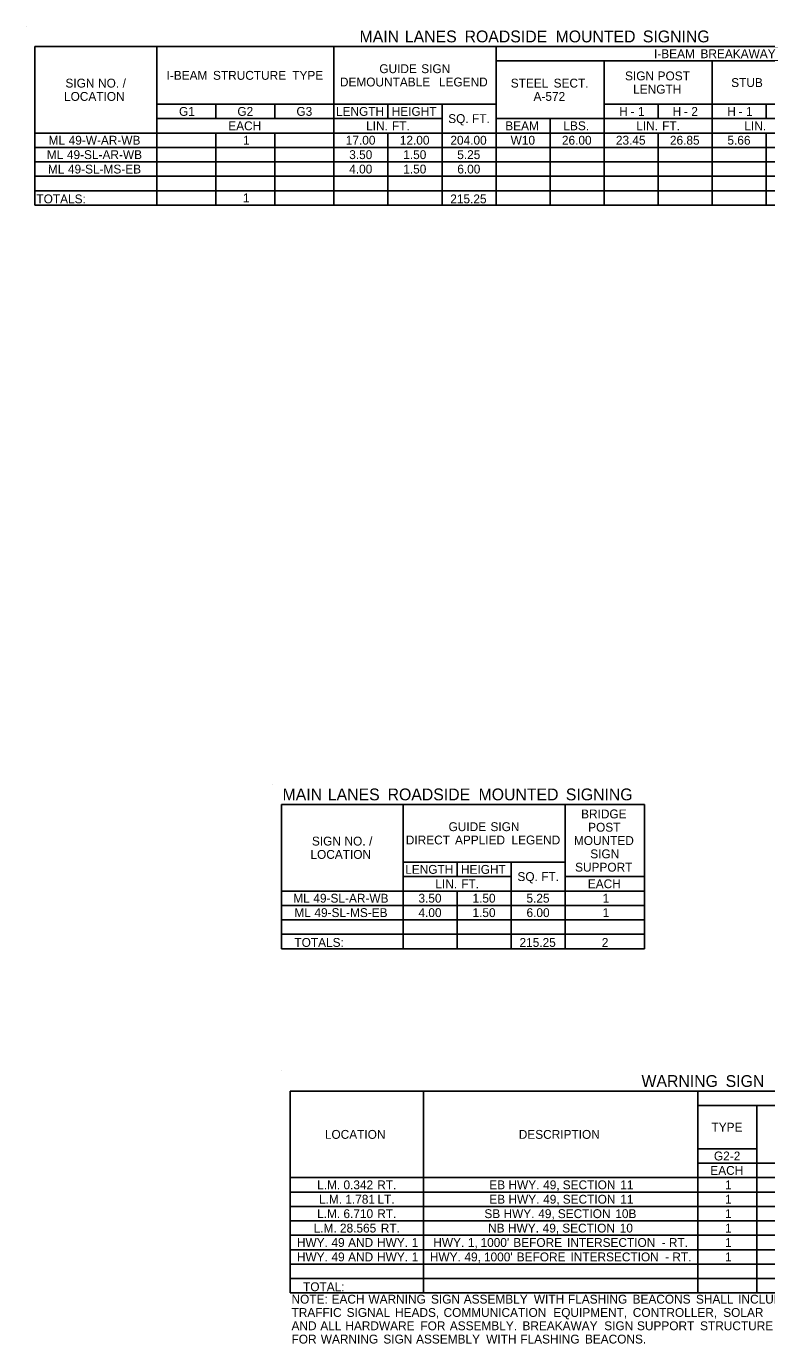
# Model space of a CAD drawing. Extents: x 229 to 4210, y 35 to 1715.
# Drawn here: x 2341 to 2842, y 368 to 1259 of the extents above; entities that cross this region are included whole.
import ezdxf

# ---------------------------------------------------------------- set-up
doc = ezdxf.new("R2010")
doc.units = 0
doc.layers.add('B_Steel Hidden', color=7, linetype='Continuous')
doc.layers.add('Default', color=7, linetype='Continuous')

msp = doc.modelspace()

# ---------------------------------------------------------------- linework, layer by layer
at = {"layer": 'B_Steel Hidden'}
for p, q in [((2341.48, 1259.36), (2341.48, 1259.36)), ((2508.25, 746.71), (2508.25, 746.71)), ((2514.1, 552.85), (2514.1, 552.85))]:
    msp.add_line(p, q, dxfattribs=at)
at = {"layer": 'Default'}
for p, q in [((2347.33, 1245.71), (3024.95, 1245.71)), ((2347.33, 1138.46), (2347.33, 1245.71)), ((2347.33, 1138.46), (2347.33, 1245.71)), ((2429.71, 1138.46), (2429.71, 1245.71)), ((2549.64, 1138.46), (2549.64, 1245.71)), ((2659.33, 1138.46), (2659.33, 1245.71)), ((2659.33, 1235.96), (3024.95, 1235.96)), ((2732.45, 1138.46), (2732.45, 1235.96)), ((2805.58, 1206.71), (2805.58, 1235.96)), ((2805.58, 1138.46), (2805.58, 1235.96)), ((2429.71, 1206.71), (2659.33, 1206.71)), ((2469.69, 1196.96), (2469.69, 1206.71)), ((2509.66, 1196.96), (2509.66, 1206.71)), ((2586.2, 1196.96), (2586.2, 1206.71)), ((2622.76, 1138.46), (2622.76, 1206.71)), ((2732.45, 1206.71), (2988.39, 1206.71)), ((2769.01, 1196.96), (2769.01, 1206.71)), ((2842.14, 1196.96), (2842.14, 1206.71)), ((2429.71, 1196.96), (2622.76, 1196.96)), ((2659.33, 1196.96), (3024.95, 1196.96)), ((2695.89, 1138.46), (2695.89, 1196.96)), ((2732.45, 1196.96), (2769.01, 1196.96)), ((2769.01, 1196.96), (2805.58, 1196.96)), ((2805.58, 1196.96), (2842.14, 1196.96)), ((2805.58, 1148.21), (2805.58, 1196.96)), ((2842.14, 1196.96), (2988.39, 1196.96)), ((2347.33, 1187.21), (3024.95, 1187.21)), ((2429.71, 1138.46), (2429.71, 1187.21)), ((2469.69, 1148.21), (2469.69, 1187.21)), ((2469.69, 1138.46), (2469.69, 1187.21)), ((2509.66, 1148.21), (2509.66, 1187.21)), ((2509.66, 1138.46), (2509.66, 1187.21)), ((2549.64, 1148.21), (2549.64, 1187.21)), ((2586.2, 1148.21), (2586.2, 1187.21)), ((2586.2, 1138.46), (2586.2, 1187.21)), ((2622.76, 1187.21), (3024.95, 1187.21)), ((2622.76, 1148.21), (2622.76, 1187.21)), ((2659.33, 1148.21), (2659.33, 1187.21)), ((2695.89, 1148.21), (2695.89, 1187.21)), ((2732.45, 1148.21), (2732.45, 1187.21)), ((2769.01, 1148.21), (2769.01, 1187.21)), ((2769.01, 1138.46), (2769.01, 1187.21)), ((2842.14, 1148.21), (2842.14, 1187.21)), ((2842.14, 1138.46), (2842.14, 1187.21)), ((2347.33, 1177.46), (3024.95, 1177.46)), ((2347.33, 1167.71), (3024.95, 1167.71)), ((2347.33, 1157.96), (3024.95, 1157.96)), ((2347.33, 1148.21), (3024.95, 1148.21)), ((2347.33, 1148.21), (3024.95, 1148.21)), ((2347.33, 1138.46), (3024.95, 1138.46)), ((2514.1, 733.06), (2759.8, 733.06)), ((2514.1, 635.56), (2514.1, 733.06)), ((2514.1, 635.56), (2514.1, 733.06)), ((2596.49, 635.56), (2596.49, 733.06)), ((2706.18, 635.56), (2706.18, 733.06)), ((2759.8, 635.56), (2759.8, 733.06)), ((2596.49, 694.06), (2706.18, 694.06)), ((2633.05, 684.31), (2633.05, 694.06)), ((2669.61, 635.56), (2669.61, 694.06)), ((2596.49, 684.31), (2669.61, 684.31)), ((2706.18, 684.31), (2759.8, 684.31)), ((2514.1, 674.56), (2706.18, 674.56)), ((2596.49, 635.56), (2596.49, 674.56)), ((2633.05, 645.31), (2633.05, 674.56)), ((2633.05, 635.56), (2633.05, 674.56)), ((2669.61, 674.56), (2759.8, 674.56)), ((2669.61, 645.31), (2669.61, 674.56)), ((2706.18, 674.56), (2759.8, 674.56)), ((2706.18, 645.31), (2706.18, 674.56)), ((2514.1, 664.81), (2759.8, 664.81)), ((2514.1, 655.06), (2759.8, 655.06)), ((2514.1, 645.31), (2759.8, 645.31)), ((2514.1, 645.31), (2759.8, 645.31)), ((2514.1, 635.56), (2759.8, 635.56)), ((2519.95, 539.2), (3293.13, 539.2)), ((2519.95, 402.7), (2519.95, 539.2)), ((2519.95, 402.7), (2519.95, 539.2)), ((2610.14, 402.7), (2610.14, 539.2)), ((2795.88, 402.7), (2795.88, 539.2)), ((2795.88, 529.45), (3201.48, 529.45)), ((2835.85, 402.7), (2835.85, 529.45)), ((2795.88, 500.2), (2835.85, 500.2)), ((2795.88, 490.45), (3164.91, 490.45)), ((2795.88, 402.7), (2795.88, 490.45)), ((2835.85, 412.45), (2835.85, 490.45)), ((2519.95, 480.7), (3293.13, 480.7)), ((2610.14, 402.7), (2610.14, 480.7)), ((2519.95, 470.95), (3293.13, 470.95)), ((2519.95, 461.2), (3293.13, 461.2)), ((2519.95, 451.45), (3293.13, 451.45)), ((2519.95, 441.7), (3293.13, 441.7)), ((2519.95, 431.95), (3293.13, 431.95)), ((2519.95, 422.2), (3293.13, 422.2)), ((2519.95, 412.45), (3293.13, 412.45)), ((2519.95, 412.45), (3293.13, 412.45)), ((2519.95, 402.7), (3293.13, 402.7))]:
    msp.add_line(p, q, dxfattribs=at)

# ---------------------------------------------------------------- texts
for s, height, p in [('MAIN', 8, (2566.96, 1248.53)), (' LANES', 8, (2594.63, 1248.53)), (' ROADSIDE', 8, (2635.07, 1248.53)), (' MOUNTED', 8, (2696.63, 1248.53)), (' SIGNING', 8, (2755.69, 1248.53)), ('I-BEAM', 6, (2766.23, 1237.83)), (' BREAKAWAY', 6, (2795.44, 1237.83)), ('GUIDE', 6, (2580.34, 1227.71)), (' SIGN', 6, (2606.47, 1227.71)), ('SIGN', 6, (2367.95, 1217.96)), (' NO.', 6, (2387.77, 1217.96)), (' /', 6, (2404.43, 1217.96)), ('I-BEAM', 6, (2436.36, 1223.21)), (' STRUCTURE', 6, (2465.56, 1223.21)), (' TYPE', 6, (2519.18, 1223.21)), ('DEMOUNTABLE', 6, (2553.66, 1218.71)), (' LEGEND', 6, (2618.45, 1218.71)), ('STEEL', 6, (2669.28, 1217.96)), (' SECT.', 6, (2696.05, 1217.96)), ('SIGN', 6, (2746.61, 1222.83)), (' POST', 6, (2766.43, 1222.83)), ('STUB', 6, (2818.44, 1218.33)), ('LOCATION', 6, (2366.97, 1208.96)), ('A-572', 6, (2684.69, 1208.96)), ('LENGTH', 6, (2752.1, 1213.83)), ('G1', 6, (2444.79, 1198.83)), ('G2', 6, (2484.3, 1198.83)), ('G3', 6, (2524.24, 1198.83)), ('LENGTH', 6, (2551.01, 1198.83)), ('HEIGHT', 6, (2588.73, 1198.83)), ('H', 6, (2742.68, 1198.83)), (' 1', 6, (2753.15, 1198.83)), ('H', 6, (2778.78, 1198.83)), (' 2', 6, (2789.25, 1198.83)), ('H', 6, (2815.81, 1198.83)), (' 1', 6, (2826.28, 1198.83)), ('EACH', 6, (2478.12, 1189.08)), ('LIN.', 6, (2571.41, 1189.08)), (' FT.', 6, (2586.67, 1189.08)), ('SQ.', 6, (2626.95, 1193.96)), (' FT.', 6, (2640.82, 1193.96)), ('BEAM', 6, (2665.56, 1189.08)), ('LBS.', 6, (2704.91, 1189.08)), (' -', 6, (2748.09, 1198.83)), ('LIN.', 6, (2754.22, 1189.08)), (' FT.', 6, (2769.48, 1189.08)), (' -', 6, (2784.19, 1198.83)), (' -', 6, (2821.22, 1198.83)), ('LIN.', 6, (2827.35, 1189.08)), ('ML', 6, (2356.53, 1179.33)), (' 49-W-AR-WB', 6, (2367.88, 1179.33)), ('1', 6, (2488.12, 1179.33)), ('17.00', 6, (2557.64, 1179.33)), ('12.00', 6, (2594.2, 1179.33)), ('204.00', 6, (2628.43, 1179.33)), ('W10', 6, (2669.19, 1179.33)), ('26.00', 6, (2703.89, 1179.33)), ('23.45', 6, (2740.42, 1179.33)), ('26.85', 6, (2776.98, 1179.33)), ('5.66', 6, (2815.89, 1179.33)), ('ML', 6, (2355.36, 1169.58)), (' 49-SL-AR-WB', 6, (2366.71, 1169.58)), ('3.50', 6, (2559.97, 1169.58)), ('1.50', 6, (2596.53, 1169.58)), ('5.25', 6, (2633.06, 1169.58)), ('ML', 6, (2356.06, 1159.83)), (' 49-SL-MS-EB', 6, (2367.4, 1159.83)), ('4.00', 6, (2559.97, 1159.83)), ('1.50', 6, (2596.53, 1159.83)), ('6.00', 6, (2633.09, 1159.83)), ('TOTALS:', 6, (2348.3, 1139.66)), ('1', 6, (2488.03, 1140.33)), ('215.25', 6, (2628.36, 1139.66)), ('MAIN', 8, (2514.85, 735.88)), (' LANES', 8, (2542.51, 735.88)), (' ROADSIDE', 8, (2582.96, 735.88)), (' MOUNTED', 8, (2644.51, 735.88)), (' SIGNING', 8, (2703.57, 735.88)), ('BRIDGE', 6, (2716.89, 723.68)), ('GUIDE', 6, (2627.19, 715.06)), (' SIGN', 6, (2653.32, 715.06)), ('POST', 6, (2721.66, 714.68)), ('SIGN', 6, (2534.72, 705.31)), (' NO.', 6, (2554.55, 705.31)), (' /', 6, (2571.2, 705.31)), ('DIRECT', 6, (2598.26, 706.06)), (' APPLIED', 6, (2629.3, 706.06)), (' LEGEND', 6, (2667.55, 706.06)), ('MOUNTED', 6, (2712, 705.68)), ('LOCATION', 6, (2533.74, 696.31)), ('SIGN', 6, (2723.08, 696.68)), ('LENGTH', 6, (2597.86, 686.18)), ('HEIGHT', 6, (2635.58, 686.18)), ('SQ.', 6, (2673.8, 681.31)), (' FT.', 6, (2687.67, 681.31)), ('SUPPORT', 6, (2712.81, 687.68)), ('LIN.', 6, (2618.26, 676.43)), (' FT.', 6, (2633.52, 676.43)), ('EACH', 6, (2721.43, 676.43)), ('ML', 6, (2522.13, 666.68)), (' 49-SL-AR-WB', 6, (2533.48, 666.68)), ('3.50', 6, (2606.82, 666.68)), ('1.50', 6, (2643.38, 666.68)), ('5.25', 6, (2679.91, 666.68)), ('1', 6, (2731.43, 666.68)), ('ML', 6, (2522.83, 656.93)), (' 49-SL-MS-EB', 6, (2534.18, 656.93)), ('4.00', 6, (2606.82, 656.93)), ('1.50', 6, (2643.38, 656.93)), ('6.00', 6, (2679.94, 656.93)), ('1', 6, (2731.43, 656.93)), ('TOTALS:', 6, (2522.88, 636.76)), ('215.25', 6, (2675.21, 636.76)), ('2', 6, (2730.87, 636.76)), ('WARNING', 8, (2757.76, 542.03)), (' SIGN', 8, (2811.72, 542.03)), ('TYPE', 6, (2805.12, 511.83)), ('LOCATION', 6, (2543.49, 506.95)), ('DESCRIPTION', 6, (2674.69, 506.95)), ('G2-2', 6, (2806.76, 492.33)), ('EACH', 6, (2804.31, 482.58)), ('L.M.', 6, (2538.28, 472.83)), (' 0.342', 6, (2553.85, 472.83)), (' RT.', 6, (2576.7, 472.83)), ('EB', 6, (2654.77, 472.83)), (' HWY.', 6, (2665.51, 472.83)), (' 49,', 6, (2688.99, 472.83)), (' SECTION', 6, (2702.22, 472.83)), (' 11', 6, (2741.13, 472.83)), ('1', 6, (2814.3, 472.83)), ('L.M.', 6, (2539.53, 463.08)), (' 1.781', 6, (2555.1, 463.08)), (' LT.', 6, (2576.85, 463.08)), ('EB', 6, (2654.77, 463.08)), (' HWY.', 6, (2665.51, 463.08)), (' 49,', 6, (2688.99, 463.08)), (' SECTION', 6, (2702.22, 463.08)), (' 11', 6, (2741.13, 463.08)), ('1', 6, (2814.3, 463.08)), ('L.M.', 6, (2538.26, 453.33)), (' 6.710', 6, (2553.83, 453.33)), (' RT.', 6, (2576.72, 453.33)), ('SB', 6, (2651.43, 453.33)), (' HWY.', 6, (2662.17, 453.33)), (' 49,', 6, (2685.65, 453.33)), (' SECTION', 6, (2698.88, 453.33)), (' 10B', 6, (2737.79, 453.33)), ('1', 6, (2814.3, 453.33)), ('L.M.', 6, (2535.9, 443.58)), (' 28.565', 6, (2551.47, 443.58)), (' RT.', 6, (2579.09, 443.58)), ('NB', 6, (2653.97, 443.58)), (' HWY.', 6, (2665.17, 443.58)), (' 49,', 6, (2688.66, 443.58)), (' SECTION', 6, (2701.89, 443.58)), (' 10', 6, (2740.79, 443.58)), ('1', 6, (2814.3, 443.58)), ('HWY.', 6, (2524.57, 433.83)), (' 49', 6, (2545.73, 433.83)), (' AND', 6, (2557, 433.83)), (' HWY.', 6, (2576.59, 433.83)), (' 1', 6, (2600.07, 433.83)), ('HWY.', 6, (2616.87, 433.83)), (' 1,', 6, (2638.02, 433.83)), (" 1000'", 6, (2646.59, 433.83)), (' BEFORE', 6, (2668.77, 433.83)), (' INTERSECTION', 6, (2705.13, 433.83)), (' RT.', 6, (2774.04, 433.83)), ('1', 6, (2814.3, 433.83)), ('HWY.', 6, (2524.57, 424.08)), (' 49', 6, (2545.73, 424.08)), (' AND', 6, (2557, 424.08)), (' HWY.', 6, (2576.59, 424.08)), (' 1', 6, (2600.07, 424.08)), ('HWY.', 6, (2614.54, 424.08)), (' 49,', 6, (2635.69, 424.08)), (" 1000'", 6, (2648.92, 424.08)), (' BEFORE', 6, (2671.1, 424.08)), (' INTERSECTION', 6, (2707.46, 424.08)), (' -', 6, (2769.19, 433.83)), (' RT.', 6, (2776.37, 424.08)), ('1', 6, (2814.3, 424.08)), (' -', 6, (2771.52, 424.08)), ('TOTAL:', 6, (2528.73, 403.9)), ('NOTE:', 6, (2520.93, 395.5)), (' EACH', 6, (2545.81, 395.5)), (' WARNING', 6, (2570.76, 395.5)), (' SIGN', 6, (2613.08, 395.5)), (' ASSEMBLY', 6, (2635.22, 395.5)), (' WITH', 6, (2682.68, 395.5)), (' FLASHING', 6, (2705.75, 395.5)), (' BEACONS', 6, (2749.48, 395.5)), (' SHALL', 6, (2792.37, 395.5)), (' INCLUDE', 6, (2820.96, 395.5)), ('TRAFFIC', 6, (2520.93, 386.5)), (' SIGNAL', 6, (2555.99, 386.5)), (' HEADS,', 6, (2588.77, 386.5)), (' COMMUNICATION', 6, (2621.57, 386.5)), (' EQUIPMENT,', 6, (2695.86, 386.5)), (' CONTROLLER,', 6, (2749.62, 386.5)), (' SOLAR', 6, (2810.82, 386.5)), ('AND', 6, (2520.93, 377.5)), (' ALL', 6, (2538.18, 377.5)), (' HARDWARE', 6, (2555.12, 377.5)), (' FOR', 6, (2605.91, 377.5)), (' ASSEMBLY.', 6, (2625.82, 377.5)), (' BREAKAWAY', 6, (2674.95, 377.5)), (' SIGN', 6, (2730.33, 377.5)), (' SUPPORT', 6, (2752.47, 377.5)), (' STRUCTURE', 6, (2795.16, 377.5)), ('FOR', 6, (2520.93, 368.5)), (' WARNING', 6, (2538.51, 368.5)), (' SIGN', 6, (2580.83, 368.5)), (' ASSEMBLY', 6, (2602.97, 368.5)), (' WITH', 6, (2650.43, 368.5)), (' FLASHING', 6, (2673.5, 368.5)), (' BEACONS.', 6, (2717.23, 368.5))]:
    msp.add_text(s, height=height, dxfattribs=at).set_placement(p)

doc.saveas('drawing.dxf')
